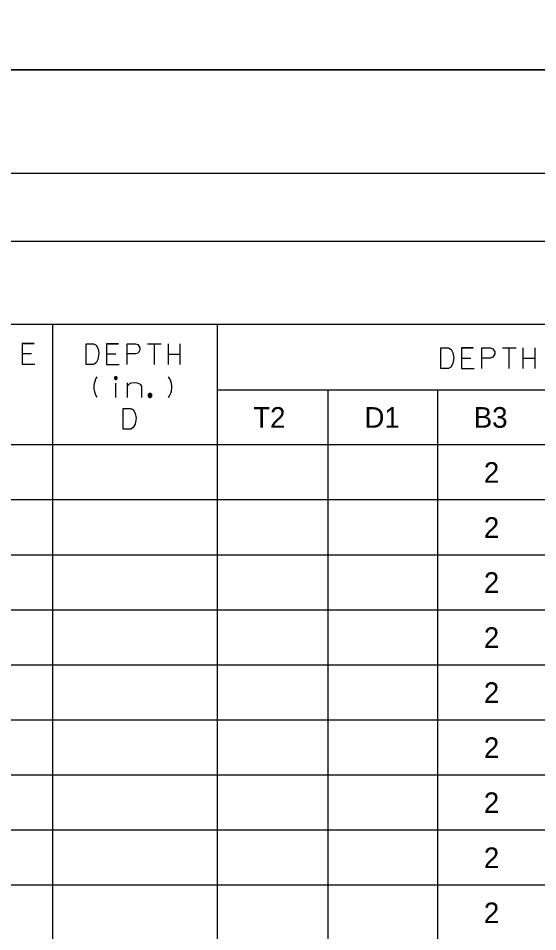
# Model space of a CAD drawing. Extents: x 635698 to 639877, y 296617 to 300175.
# Drawn here: x 638959 to 639034.5, y 298726.5 to 298859.3 of the extents above; entities that cross this region are included whole.
import ezdxf

# ---------------------------------------------------------------- set-up
doc = ezdxf.new("R2010")
doc.units = 0
for name, color, linetype in [('1', 7, 'Continuous'), ('2', 7, 'Continuous'), ('3', 7, 'Continuous'), ('PLT-BNDY', 7, 'Continuous')]:
    doc.layers.add(name, color=color, linetype=linetype)

msp = doc.modelspace()

# ---------------------------------------------------------------- linework, layer by layer
at = {"layer": '1'}
for points in [[(638961.33, 298812.05), (638959.6, 298812.05), (638959.6, 298809.05), (638961.44, 298809.05)], [(638959.6, 298812.05), (638961.33, 298812.05)], [(638959.6, 298810.57), (638960.95, 298810.57)], [(638959.6, 298810.57), (638960.95, 298810.57)], [(638970.52, 298804.21), (638970.33, 298804.51), (638970.19, 298804.84), (638970.1, 298805.17), (638970.05, 298805.53), (638970.05, 298805.88), (638970.1, 298806.24), (638970.19, 298806.57), (638970.33, 298806.9), (638970.52, 298807.21)], [(638973.4, 298807.01), (638973.4, 298807.03), (638973.4, 298807.05), (638973.39, 298807.07), (638973.38, 298807.09), (638973.37, 298807.11), (638973.36, 298807.13), (638973.35, 298807.14), (638973.34, 298807.16), (638973.32, 298807.17), (638973.3, 298807.18), (638973.28, 298807.19), (638973.26, 298807.2), (638973.24, 298807.2), (638973.22, 298807.21), (638973.2, 298807.21), (638973.18, 298807.21), (638973.16, 298807.2), (638973.14, 298807.2), (638973.12, 298807.19), (638973.1, 298807.18), (638973.09, 298807.17), (638973.07, 298807.16), (638973.06, 298807.14), (638973.04, 298807.13), (638973.03, 298807.11), (638973.02, 298807.09), (638973.01, 298807.07), (638973.01, 298807.05), (638973.01, 298807.03), (638973, 298807.01), (638973.01, 298806.99), (638973.01, 298806.97), (638973.01, 298806.95), (638973.02, 298806.93), (638973.03, 298806.91), (638973.04, 298806.89), (638973.06, 298806.88), (638973.07, 298806.86), (638973.09, 298806.85), (638973.1, 298806.84), (638973.12, 298806.83), (638973.14, 298806.82), (638973.16, 298806.81), (638973.18, 298806.81), (638973.2, 298806.81), (638973.22, 298806.81), (638973.24, 298806.81), (638973.26, 298806.82), (638973.28, 298806.83), (638973.3, 298806.84), (638973.32, 298806.85), (638973.34, 298806.86), (638973.35, 298806.88), (638973.36, 298806.89), (638973.37, 298806.91), (638973.38, 298806.93), (638973.39, 298806.95), (638973.4, 298806.97), (638973.4, 298806.99), (638973.4, 298807.01)], [(638973.34, 298807.01), (638973.34, 298807.02), (638973.34, 298807.04), (638973.33, 298807.05), (638973.33, 298807.06), (638973.32, 298807.08), (638973.31, 298807.09), (638973.31, 298807.1), (638973.3, 298807.11), (638973.28, 298807.12), (638973.27, 298807.13), (638973.26, 298807.13), (638973.25, 298807.14), (638973.23, 298807.14), (638973.22, 298807.15), (638973.2, 298807.15), (638973.19, 298807.15), (638973.17, 298807.14), (638973.16, 298807.14), (638973.15, 298807.13), (638973.13, 298807.13), (638973.12, 298807.12), (638973.11, 298807.11), (638973.1, 298807.1), (638973.09, 298807.09), (638973.08, 298807.08), (638973.08, 298807.06), (638973.07, 298807.05), (638973.07, 298807.04), (638973.07, 298807.02), (638973.06, 298807.01), (638973.07, 298806.99), (638973.07, 298806.98), (638973.07, 298806.97), (638973.08, 298806.95), (638973.08, 298806.94), (638973.09, 298806.93), (638973.1, 298806.92), (638973.11, 298806.91), (638973.12, 298806.9), (638973.13, 298806.89), (638973.15, 298806.88), (638973.16, 298806.88), (638973.17, 298806.87), (638973.19, 298806.87), (638973.2, 298806.87), (638973.22, 298806.87), (638973.23, 298806.87), (638973.25, 298806.88), (638973.26, 298806.88), (638973.27, 298806.89), (638973.28, 298806.9), (638973.3, 298806.91), (638973.31, 298806.92), (638973.31, 298806.93), (638973.32, 298806.94), (638973.33, 298806.95), (638973.33, 298806.97), (638973.34, 298806.98), (638973.34, 298806.99), (638973.34, 298807.01)], [(638973.28, 298807.01), (638973.28, 298807.02), (638973.28, 298807.02), (638973.28, 298807.03), (638973.27, 298807.04), (638973.27, 298807.05), (638973.27, 298807.05), (638973.26, 298807.06), (638973.25, 298807.07), (638973.25, 298807.07), (638973.24, 298807.08), (638973.23, 298807.08), (638973.23, 298807.08), (638973.22, 298807.08), (638973.21, 298807.09), (638973.2, 298807.09), (638973.19, 298807.09), (638973.19, 298807.08), (638973.18, 298807.08), (638973.17, 298807.08), (638973.16, 298807.08), (638973.16, 298807.07), (638973.15, 298807.07), (638973.14, 298807.06), (638973.14, 298807.05), (638973.14, 298807.05), (638973.13, 298807.04), (638973.13, 298807.03), (638973.13, 298807.02), (638973.13, 298807.02), (638973.12, 298807.01), (638973.13, 298807), (638973.13, 298806.99), (638973.13, 298806.98), (638973.13, 298806.98), (638973.14, 298806.97), (638973.14, 298806.96), (638973.14, 298806.96), (638973.15, 298806.95), (638973.16, 298806.95), (638973.16, 298806.94), (638973.17, 298806.94), (638973.18, 298806.93), (638973.19, 298806.93), (638973.19, 298806.93), (638973.2, 298806.93), (638973.21, 298806.93), (638973.22, 298806.93), (638973.23, 298806.93), (638973.23, 298806.94), (638973.24, 298806.94), (638973.25, 298806.95), (638973.25, 298806.95), (638973.26, 298806.96), (638973.27, 298806.96), (638973.27, 298806.97), (638973.27, 298806.98), (638973.28, 298806.98), (638973.28, 298806.99), (638973.28, 298807), (638973.28, 298807.01)], [(638973.22, 298807.01), (638973.22, 298807.01), (638973.22, 298807.01), (638973.22, 298807.01), (638973.22, 298807.02), (638973.22, 298807.02), (638973.22, 298807.02), (638973.22, 298807.02), (638973.22, 298807.02), (638973.21, 298807.02), (638973.21, 298807.02), (638973.21, 298807.03), (638973.21, 298807.03), (638973.21, 298807.03), (638973.2, 298807.03), (638973.2, 298807.03), (638973.2, 298807.03), (638973.2, 298807.03), (638973.2, 298807.03), (638973.2, 298807.03), (638973.19, 298807.02), (638973.19, 298807.02), (638973.19, 298807.02), (638973.19, 298807.02), (638973.19, 298807.02), (638973.19, 298807.02), (638973.19, 298807.02), (638973.19, 298807.01), (638973.19, 298807.01), (638973.18, 298807.01), (638973.18, 298807.01), (638973.18, 298807.01), (638973.19, 298807.01), (638973.19, 298807), (638973.19, 298807), (638973.19, 298807), (638973.19, 298807), (638973.19, 298807), (638973.19, 298807), (638973.19, 298806.99), (638973.19, 298806.99), (638973.2, 298806.99), (638973.2, 298806.99), (638973.2, 298806.99), (638973.2, 298806.99), (638973.2, 298806.99), (638973.2, 298806.99), (638973.21, 298806.99), (638973.21, 298806.99), (638973.21, 298806.99), (638973.21, 298806.99), (638973.21, 298806.99), (638973.22, 298807), (638973.22, 298807), (638973.22, 298807), (638973.22, 298807), (638973.22, 298807), (638973.22, 298807), (638973.22, 298807.01), (638973.22, 298807.01), (638973.22, 298807.01)], [(638980.87, 298804.21), (638981.06, 298804.51), (638981.2, 298804.84), (638981.29, 298805.17), (638981.34, 298805.53), (638981.34, 298805.88), (638981.29, 298806.24), (638981.2, 298806.57), (638981.06, 298806.9), (638980.87, 298807.21)], [(638973.2, 298804.21), (638973.2, 298806.29)], [(638974.91, 298805.84), (638975.07, 298806.05), (638975.24, 298806.21), (638975.45, 298806.31), (638975.92, 298806.38), (638976.32, 298806.31), (638976.73, 298806.12), (638976.85, 298806), (638976.92, 298805.81), (638976.92, 298804.21)], [(638974.91, 298804.21), (638974.91, 298806.31)], [(638978.46, 298804.49), (638978.46, 298804.52), (638978.45, 298804.55), (638978.44, 298804.58), (638978.43, 298804.61), (638978.42, 298804.63), (638978.4, 298804.66), (638978.38, 298804.68), (638978.36, 298804.7), (638978.34, 298804.72), (638978.31, 298804.74), (638978.29, 298804.75), (638978.26, 298804.76), (638978.23, 298804.77), (638978.2, 298804.77), (638978.17, 298804.78), (638978.14, 298804.77), (638978.11, 298804.77), (638978.08, 298804.76), (638978.06, 298804.75), (638978.03, 298804.74), (638978, 298804.72), (638977.98, 298804.7), (638977.96, 298804.68), (638977.94, 298804.66), (638977.92, 298804.63), (638977.91, 298804.61), (638977.9, 298804.58), (638977.89, 298804.55), (638977.89, 298804.52), (638977.89, 298804.49), (638977.89, 298804.46), (638977.89, 298804.43), (638977.9, 298804.4), (638977.91, 298804.37), (638977.92, 298804.35), (638977.94, 298804.32), (638977.96, 298804.3), (638977.98, 298804.28), (638978, 298804.26), (638978.03, 298804.24), (638978.06, 298804.23), (638978.08, 298804.22), (638978.11, 298804.21), (638978.14, 298804.21), (638978.17, 298804.21), (638978.2, 298804.21), (638978.23, 298804.21), (638978.26, 298804.22), (638978.29, 298804.23), (638978.31, 298804.24), (638978.34, 298804.26), (638978.36, 298804.28), (638978.38, 298804.3), (638978.4, 298804.32), (638978.42, 298804.35), (638978.43, 298804.37), (638978.44, 298804.4), (638978.45, 298804.43), (638978.46, 298804.46), (638978.46, 298804.49)], [(638978.4, 298804.49), (638978.4, 298804.51), (638978.39, 298804.54), (638978.39, 298804.56), (638978.38, 298804.58), (638978.37, 298804.6), (638978.35, 298804.62), (638978.34, 298804.64), (638978.32, 298804.66), (638978.3, 298804.67), (638978.28, 298804.69), (638978.26, 298804.7), (638978.24, 298804.7), (638978.22, 298804.71), (638978.19, 298804.71), (638978.17, 298804.72), (638978.15, 298804.71), (638978.12, 298804.71), (638978.1, 298804.7), (638978.08, 298804.7), (638978.06, 298804.69), (638978.04, 298804.67), (638978.02, 298804.66), (638978, 298804.64), (638977.99, 298804.62), (638977.98, 298804.6), (638977.97, 298804.58), (638977.96, 298804.56), (638977.95, 298804.54), (638977.95, 298804.51), (638977.95, 298804.49), (638977.95, 298804.47), (638977.95, 298804.44), (638977.96, 298804.42), (638977.97, 298804.4), (638977.98, 298804.38), (638977.99, 298804.36), (638978, 298804.34), (638978.02, 298804.32), (638978.04, 298804.31), (638978.06, 298804.3), (638978.08, 298804.28), (638978.1, 298804.28), (638978.12, 298804.27), (638978.15, 298804.27), (638978.17, 298804.27), (638978.19, 298804.27), (638978.22, 298804.27), (638978.24, 298804.28), (638978.26, 298804.28), (638978.28, 298804.3), (638978.3, 298804.31), (638978.32, 298804.32), (638978.34, 298804.34), (638978.35, 298804.36), (638978.37, 298804.38), (638978.38, 298804.4), (638978.39, 298804.42), (638978.39, 298804.44), (638978.4, 298804.47), (638978.4, 298804.49)], [(638978.34, 298804.49), (638978.34, 298804.51), (638978.33, 298804.52), (638978.33, 298804.54), (638978.32, 298804.56), (638978.31, 298804.57), (638978.3, 298804.59), (638978.29, 298804.6), (638978.28, 298804.61), (638978.27, 298804.62), (638978.25, 298804.63), (638978.24, 298804.64), (638978.22, 298804.65), (638978.21, 298804.65), (638978.19, 298804.65), (638978.17, 298804.66), (638978.15, 298804.65), (638978.14, 298804.65), (638978.12, 298804.65), (638978.1, 298804.64), (638978.09, 298804.63), (638978.07, 298804.62), (638978.06, 298804.61), (638978.05, 298804.6), (638978.04, 298804.59), (638978.03, 298804.57), (638978.02, 298804.56), (638978.01, 298804.54), (638978.01, 298804.52), (638978.01, 298804.51), (638978.01, 298804.49), (638978.01, 298804.47), (638978.01, 298804.46), (638978.01, 298804.44), (638978.02, 298804.42), (638978.03, 298804.41), (638978.04, 298804.39), (638978.05, 298804.38), (638978.06, 298804.37), (638978.07, 298804.36), (638978.09, 298804.35), (638978.1, 298804.34), (638978.12, 298804.33), (638978.14, 298804.33), (638978.15, 298804.33), (638978.17, 298804.33), (638978.19, 298804.33), (638978.21, 298804.33), (638978.22, 298804.33), (638978.24, 298804.34), (638978.25, 298804.35), (638978.27, 298804.36), (638978.28, 298804.37), (638978.29, 298804.38), (638978.3, 298804.39), (638978.31, 298804.41), (638978.32, 298804.42), (638978.33, 298804.44), (638978.33, 298804.46), (638978.34, 298804.47), (638978.34, 298804.49)], [(638978.28, 298804.49), (638978.28, 298804.5), (638978.27, 298804.51), (638978.27, 298804.52), (638978.27, 298804.53), (638978.26, 298804.54), (638978.26, 298804.55), (638978.25, 298804.56), (638978.24, 298804.57), (638978.23, 298804.58), (638978.22, 298804.58), (638978.21, 298804.59), (638978.2, 298804.59), (638978.19, 298804.59), (638978.18, 298804.6), (638978.17, 298804.6), (638978.16, 298804.6), (638978.15, 298804.59), (638978.14, 298804.59), (638978.13, 298804.59), (638978.12, 298804.58), (638978.11, 298804.58), (638978.1, 298804.57), (638978.09, 298804.56), (638978.09, 298804.55), (638978.08, 298804.54), (638978.08, 298804.53), (638978.07, 298804.52), (638978.07, 298804.51), (638978.07, 298804.5), (638978.07, 298804.49), (638978.07, 298804.48), (638978.07, 298804.47), (638978.07, 298804.46), (638978.08, 298804.45), (638978.08, 298804.44), (638978.09, 298804.43), (638978.09, 298804.42), (638978.1, 298804.41), (638978.11, 298804.41), (638978.12, 298804.4), (638978.13, 298804.39), (638978.14, 298804.39), (638978.15, 298804.39), (638978.16, 298804.39), (638978.17, 298804.39), (638978.18, 298804.39), (638978.19, 298804.39), (638978.2, 298804.39), (638978.21, 298804.39), (638978.22, 298804.4), (638978.23, 298804.41), (638978.24, 298804.41), (638978.25, 298804.42), (638978.26, 298804.43), (638978.26, 298804.44), (638978.27, 298804.45), (638978.27, 298804.46), (638978.27, 298804.47), (638978.28, 298804.48), (638978.28, 298804.49)], [(638978.22, 298804.49), (638978.22, 298804.5), (638978.22, 298804.5), (638978.21, 298804.5), (638978.21, 298804.51), (638978.21, 298804.51), (638978.21, 298804.52), (638978.2, 298804.52), (638978.2, 298804.52), (638978.2, 298804.53), (638978.19, 298804.53), (638978.19, 298804.53), (638978.19, 298804.53), (638978.18, 298804.53), (638978.18, 298804.54), (638978.17, 298804.54), (638978.17, 298804.54), (638978.16, 298804.53), (638978.16, 298804.53), (638978.15, 298804.53), (638978.15, 298804.53), (638978.15, 298804.53), (638978.14, 298804.52), (638978.14, 298804.52), (638978.13, 298804.52), (638978.13, 298804.51), (638978.13, 298804.51), (638978.13, 298804.5), (638978.13, 298804.5), (638978.13, 298804.5), (638978.13, 298804.49), (638978.13, 298804.49), (638978.13, 298804.48), (638978.13, 298804.48), (638978.13, 298804.47), (638978.13, 298804.47), (638978.13, 298804.46), (638978.14, 298804.46), (638978.14, 298804.46), (638978.15, 298804.45), (638978.15, 298804.45), (638978.15, 298804.45), (638978.16, 298804.45), (638978.16, 298804.45), (638978.17, 298804.45), (638978.17, 298804.45), (638978.18, 298804.45), (638978.18, 298804.45), (638978.19, 298804.45), (638978.19, 298804.45), (638978.19, 298804.45), (638978.2, 298804.45), (638978.2, 298804.46), (638978.2, 298804.46), (638978.21, 298804.46), (638978.21, 298804.47), (638978.21, 298804.47), (638978.21, 298804.48), (638978.22, 298804.48), (638978.22, 298804.49), (638978.22, 298804.49)], [(638974.28, 298802.6), (638975.37, 298802.6), (638975.77, 298802.39), (638976.03, 298801.87), (638976.15, 298801.18), (638976.01, 298800.33), (638975.75, 298799.81), (638975.37, 298799.6), (638974.28, 298799.6), (638974.28, 298802.6)]]:
    msp.add_lwpolyline(points, dxfattribs=at)
at = {"layer": '2'}
for p, q in [((638842.3, 298836.8), (639628.3, 298836.8)), ((639405.11, 298826.88), (638853.27, 298826.88)), ((639405.11, 298814.79), (638853.27, 298814.79)), ((638964.02, 298814.79), (638964.02, 298581.29)), ((638987.91, 298814.79), (638987.91, 298581.29)), ((638987.91, 298805.29), (639100.52, 298805.29)), ((639004, 298805.29), (639004, 298581.29)), ((639019.92, 298805.29), (639019.92, 298581.29)), ((639405.11, 298797.29), (638853.27, 298797.29)), ((639405.11, 298789.29), (638853.27, 298789.29)), ((639405.11, 298781.29), (638853.27, 298781.29)), ((639405.11, 298773.29), (638853.27, 298773.29)), ((639405.11, 298765.29), (638853.27, 298765.29)), ((639405.11, 298757.29), (638853.27, 298757.29)), ((639405.11, 298749.29), (638853.27, 298749.29)), ((639405.11, 298741.29), (638853.27, 298741.29)), ((639405.11, 298733.29), (638853.27, 298733.29))]:
    msp.add_line(p, q, dxfattribs=at)
at = {"layer": '3'}
for points in [[(638968.88, 298812), (638969.97, 298812), (638970.37, 298811.79), (638970.63, 298811.27), (638970.75, 298810.58), (638970.61, 298809.73), (638970.35, 298809.21), (638969.97, 298809), (638968.88, 298809), (638968.88, 298812)], [(638973.59, 298812), (638971.86, 298812), (638971.86, 298809), (638973.71, 298809)], [(638971.86, 298812), (638973.59, 298812)], [(638974.84, 298809), (638974.84, 298812), (638976.05, 298812), (638976.4, 298811.88), (638976.71, 298811.41), (638976.71, 298811.13), (638976.43, 298810.65), (638976.05, 298810.53), (638974.84, 298810.53)], [(638977.82, 298812), (638979.81, 298812)], [(638978.82, 298809), (638978.82, 298812)], [(638978.82, 298809), (638978.82, 298812)], [(638980.8, 298812), (638980.8, 298809)], [(638982.51, 298812), (638982.51, 298809)], [(639020.41, 298811.39), (639021.49, 298811.39), (639021.9, 298811.18), (639022.16, 298810.66), (639022.27, 298809.97), (639022.13, 298809.12), (639021.87, 298808.6), (639021.49, 298808.39), (639020.41, 298808.39), (639020.41, 298811.39)], [(639025.11, 298811.39), (639023.39, 298811.39), (639023.39, 298808.39), (639025.23, 298808.39)], [(639023.39, 298811.39), (639025.11, 298811.39)], [(639026.37, 298808.39), (639026.37, 298811.39), (639027.57, 298811.39), (639027.93, 298811.27), (639028.23, 298810.8), (639028.23, 298810.52), (639027.95, 298810.04), (639027.57, 298809.92), (639026.37, 298809.92)], [(639029.35, 298811.39), (639031.33, 298811.39)], [(639030.34, 298808.39), (639030.34, 298811.39)], [(639030.34, 298808.39), (639030.34, 298811.39)], [(639032.32, 298811.39), (639032.32, 298808.39)], [(639034.03, 298811.39), (639034.03, 298808.39)], [(638971.86, 298810.51), (638973.21, 298810.51)], [(638971.86, 298810.51), (638973.21, 298810.51)], [(638980.8, 298810.49), (638982.51, 298810.49)], [(639023.39, 298809.9), (639024.74, 298809.9)], [(639023.39, 298809.9), (639024.74, 298809.9)], [(639032.32, 298809.88), (639034.03, 298809.88)]]:
    msp.add_lwpolyline(points, dxfattribs=at)
at = {"layer": 'PLT-BNDY'}
for points in [[(638802.3, 299445.8), (639643.3, 299445.8), (639643.3, 298851.8), (638802.3, 298851.8)], [(638802.3, 298851.8), (639643.3, 298851.8), (639643.3, 298257.8), (638802.3, 298257.8)]]:
    msp.add_lwpolyline(points, close=True, dxfattribs=at)

# ---------------------------------------------------------------- texts
at = {"layer": '2'}
for s, p in [('T2', (638993.16, 298799.79)), ('D1', (639009.31, 298799.79)), ('B3', (639025.18, 298799.79)), ('2', (639026.65, 298791.79)), ('2', (639026.65, 298783.79)), ('2', (639026.65, 298775.79)), ('2', (639026.65, 298767.79)), ('2', (639026.65, 298759.79)), ('2', (639026.65, 298751.79)), ('2', (639026.65, 298743.79)), ('2', (639026.65, 298735.79)), ('2', (639026.65, 298727.79))]:
    msp.add_text(s, height=3, dxfattribs=at).set_placement(p)

doc.saveas('drawing.dxf')
